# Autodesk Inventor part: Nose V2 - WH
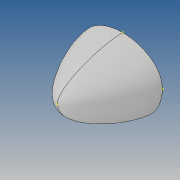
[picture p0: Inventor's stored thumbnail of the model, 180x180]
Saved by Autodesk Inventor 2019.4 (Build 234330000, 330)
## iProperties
Created: 2019-10
Part Number: Nose V2 - WH
Material: Generic
Document SubType Name: Modeling
Designer: The Dude
Density: 1 g/cm^3
Appearance: Default
Mass: 539094 g
Surface Area: 36796.9 cm^2
Volume: 539094 cm^3
Mass: 539.09
ipwModelExtentsX: 1327.8
ipwModelExtentsY: 1018
ipwModelExtentsZ: 994.2
ipwMass: 539.094
ipwArea: 3679690.216 mm^2
ipwVolume: 539094459.976 mm^3
Author: The Dude
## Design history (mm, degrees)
sketch "Sketch1"
  geometry: L1 (0, 0)-(0, -994); L2 (0, -7452)-(0, -7452); L3 (0, -7452)-(0, -7526)
  constraints: 6 end point, 2 vertical
  dimensions: "d0" = 994 distance of L1.start L1.end
workplane "Work Plane1 Former 1"
sketch "Sketch2 Former 1"
  geometry: L1 (0, 0)-(0, 444); L2 (0, 0)-(0, -574); L3 (0, 0)-(-604, 0); L4 (0, 0)-(604, 0); L5 (-604, 180.558)-(-604, -180.558); L6 (-237.304, -574)-(237.304, -574); L7 (237.304, 444)-(-237.304, 444); A1 r 461.221 centre (-142.779, 0) between (-582.92, 137.844) and (-582.92, -137.844); A2 r 686.73 centre (0, 112.73) between (-182.98, -549.174) and (182.98, -549.174); A3 r 817.208 centre (0, -373.208) between (184.919, 422.803) and (-184.919, 422.803)
  constraints: 14 end point, 6 midpoint, 4 horizontal, 3 centre point, 3 point on circle, 3 vertical, 5 other
  dimensions: "d17" = 444 distance of L1.end L1.start; "d18" = 574 distance of L2.end L1.start; "d19" = 604 distance of L1.start L3.end; "d20" = 604 distance of L1.start L4.end; "d30" = 11.04 dimension on L6.start L6.end; "d32" = 8.4 dimension on L5.start L5.end; "d33" = 90 deg angle of L3 L5
workpoint "Work Point6"
workpoint "Work Point4"
workpoint "Work Point5"
sketch "Sketch3 Guideline Top Bottom"
  geometry: L1 (-574, -900.165)-(-574, -1087.835); L2 (85.893, 9.028)-(-85.893, -9.028); L3 (-46.835, 0)-(46.835, 0); L4 (444, -893.944)-(444, -1094.056); L5 (-980.126, -994)-(811.381, -994) reference; L6 (0, 0)-(0, -994); A1 r 689.454 centre (115.454, -994) between (-569.949, -919.373) and (-569.949, -1068.627); A2 r 290.489 centre (30.364, -288.897) between (67.673, -0.815) and (-66.025, -14.867); A3 r 100.679 centre (0, -100.679) between (35.115, -6.322) and (-35.115, -6.322); A4 r 801.675 centre (-357.675, -994) between (440.034, -1073.649) and (440.034, -914.351); 6 further points
  constraints: 10 end point, 8 midpoint, 4 centre point, 4 point on circle, 3 coincident, 1 horizontal, 1 perpendicular, 1 point on line, 1 vertical, 7 other
  dimensions: "d38" = 8.04 dimension on L1.start L1.end; "d39" = 90 deg angle of L5 L1; "d40" = 7.4 dimension on L2.start L2.end; "d41" = 84 deg angle of L6 L2; "d42" = 4.4 dimension on L3.start L3.end; "d43" = 90 deg angle of L6 L3; "d44" = 9.4 dimension on L4.start L4.end; "d45" = 90 deg angle of L5 L4
workpoint "Work Point7 Right Former 1"
workpoint "Work Point8 Left Former 1"
sketch "Sketch4 Guideline Left Right"
  geometry: L1 (604, -1194.027)-(604, -793.973); L2 (604, -994)-(-604, -994); L3 (0, 0)-(0, -994) reference; L4 (93.629, 0.196)-(-93.629, -0.196); A1 r 399.936 centre (204.064, -994) between (575.38, -1142.57) and (575.38, -845.43); A2 r 143.747 centre (0.3, -143.746) between (66.46, -16.13) and (-66.392, -16.407); 3 further points
  constraints: 6 end point, 4 midpoint, 2 centre point, 2 point on circle, 1 coincident, 1 horizontal, 1 point on line, 1 vertical, 5 other
  dimensions: "d47" = 9.4 dimension on L1.start L1.end; "d50" = 90 deg angle of L2 L1
node "3D-Skizze1"
feature "Extrusionsfläche1" dims "d61" = 100, "d62" = 0
feature "Extrusionsfläche2" dims "d63" = 100, "d64" = 0
feature "Erhabene Fläche3" dims "d85" = 10, "d86" = 90 deg, "d87" = 0, "d88" = 90 deg, "d89" = 10, "d90" = 90 deg, "d91" = 0, "d92" = 90 deg
  node "Kanten1"
  node "Kanten2"
mirror "Spiegeln2"
feature "Formen3"
feature "Fläche löschen4"
feature "Fläche löschen5"
node "Volumenkörper7"
node "Flä3"
node "Flä4"
node "Flä7"
node "Flä8"
node "Volumenkörper3"
feature "Erhabene Fläche4"
other parameters: "d9" = -994
